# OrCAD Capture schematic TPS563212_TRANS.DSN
size D; title: TPS563212: 4.2-V to 18-V Input, 3-A Synchronous Buck; rev: 1.0; note: Datasheet: SLUSEH9     EVM: SLUUCK3; note: Synchronous Step Down Converter; note: Converter in a SOT-5X3 Package
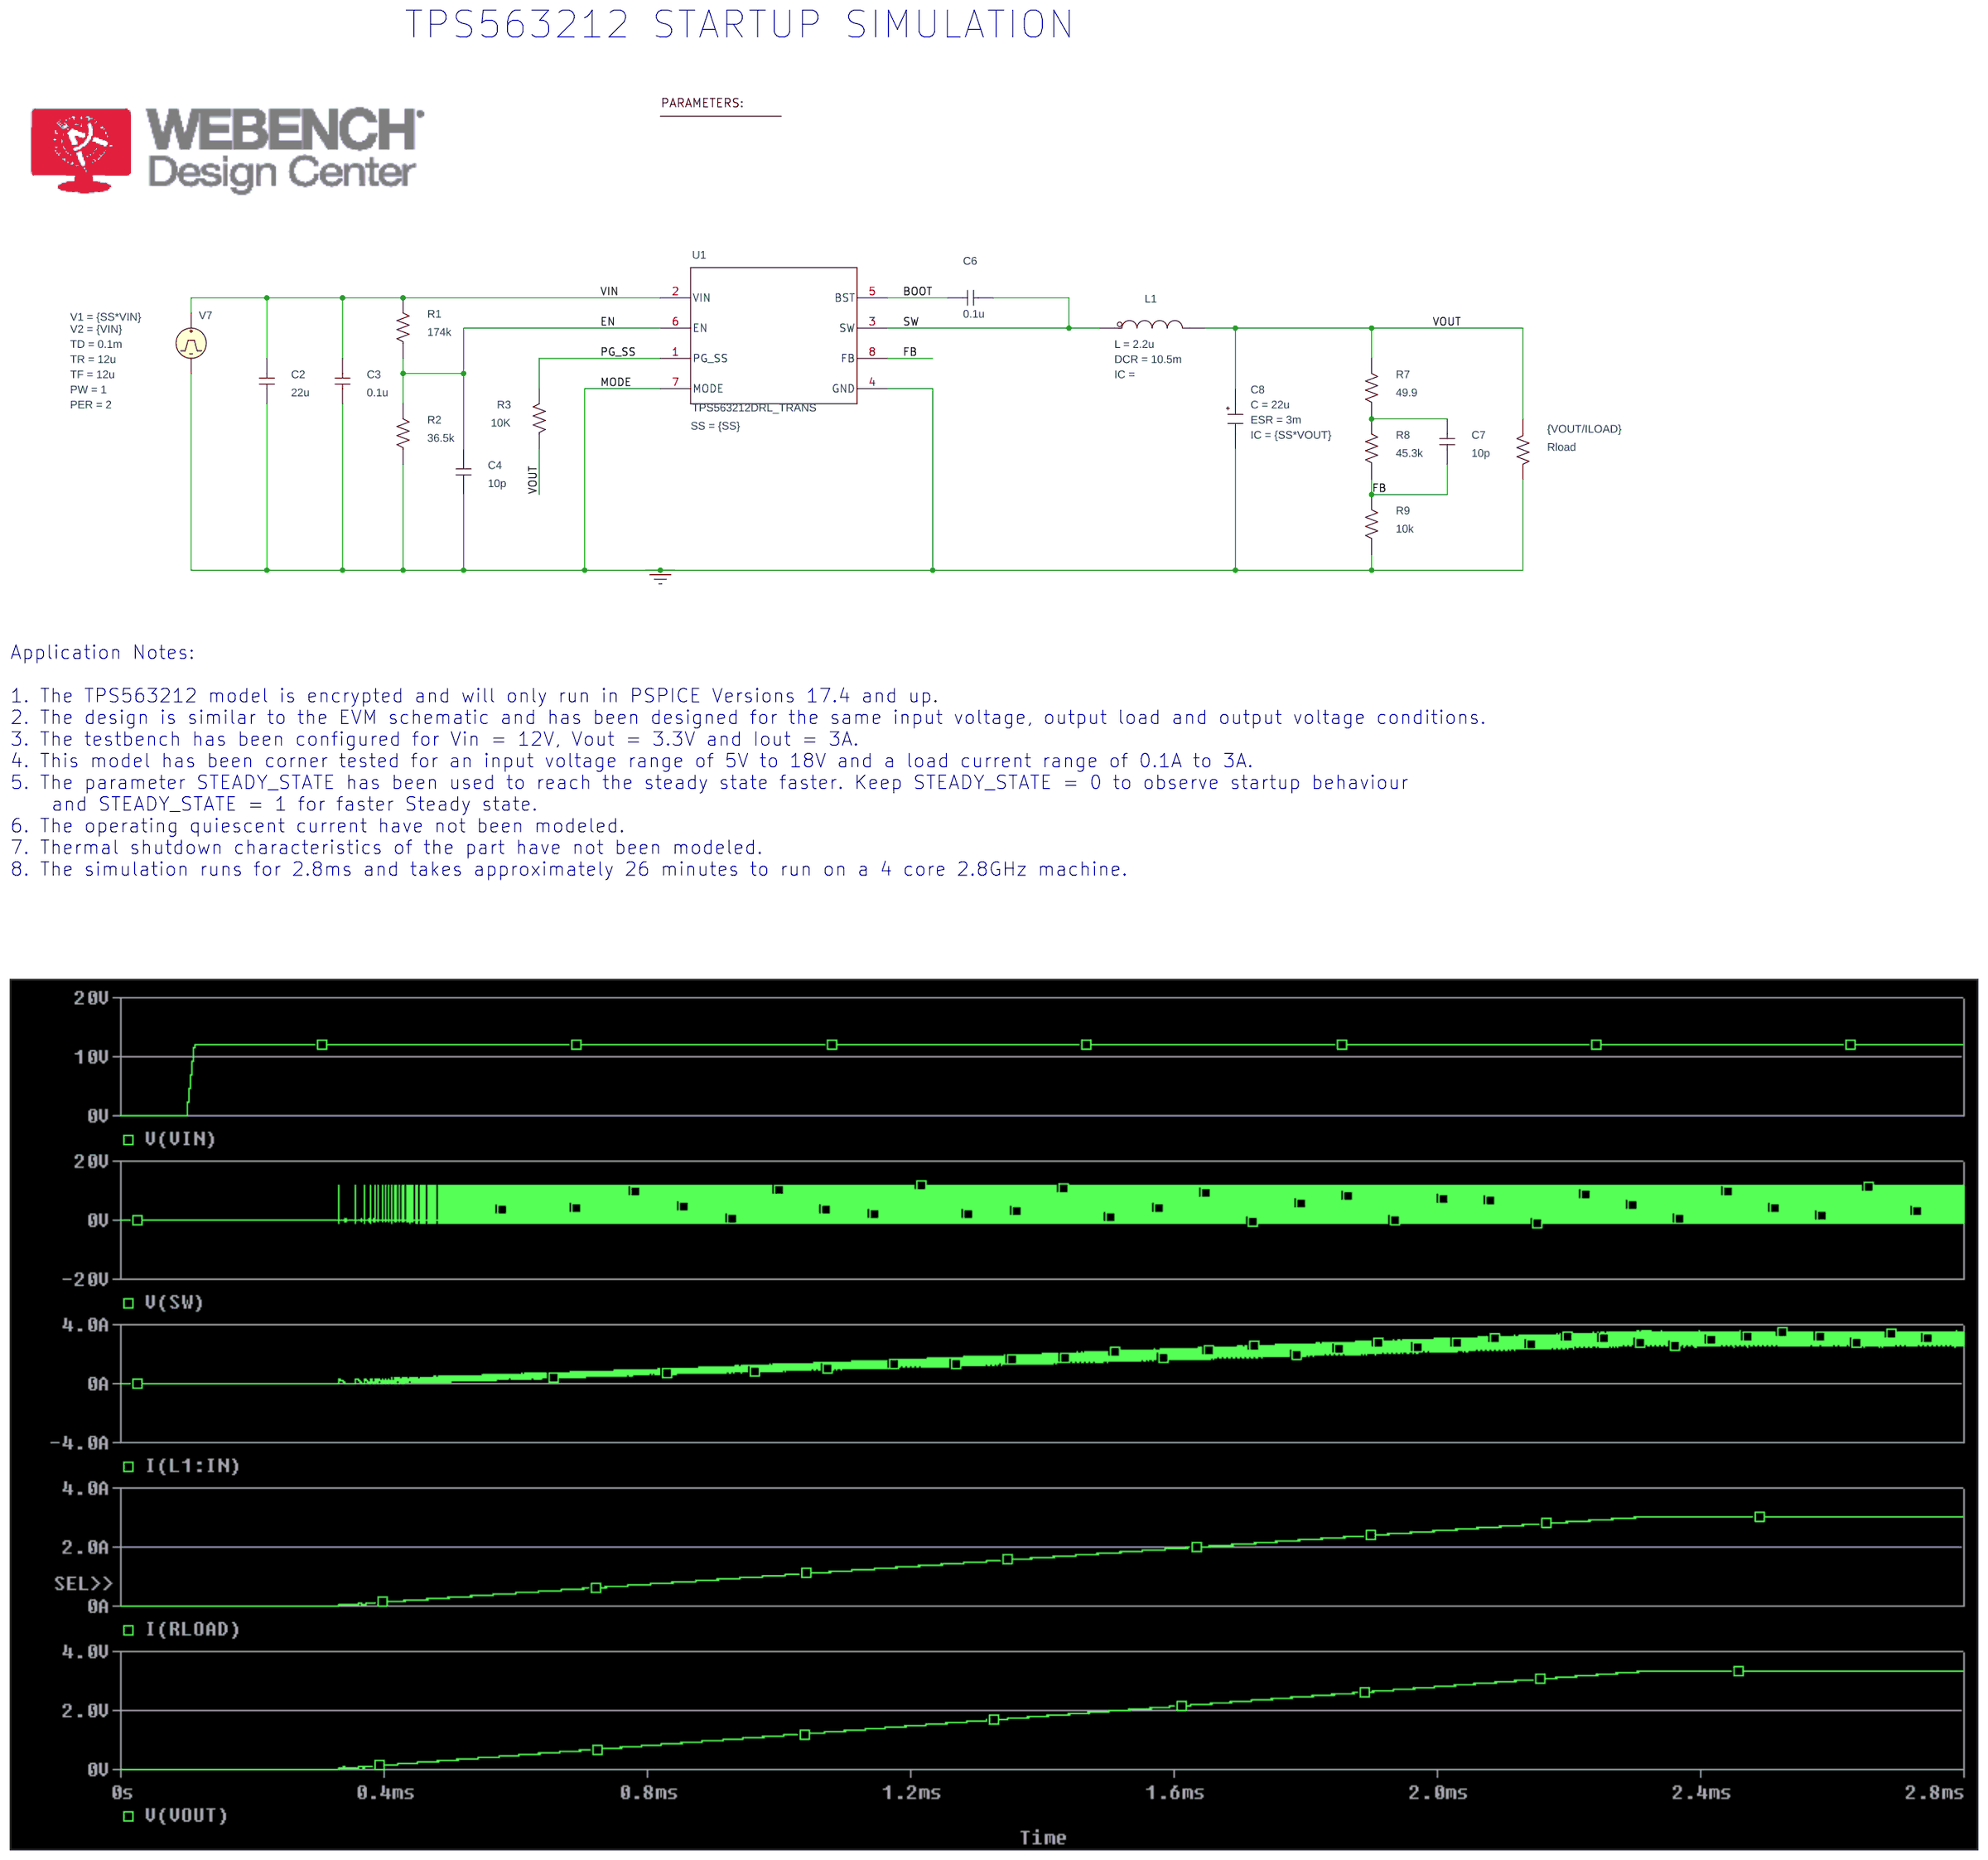
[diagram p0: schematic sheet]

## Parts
1  PARAM
C2  22u  [CK05]
C3  0.1u  [CK05]
C4  10p  [cap196]
C6  0.1u  [CK05]
C7  10p  [cap196]
C8  CESR
L1  LDCR
R1  174k  [RC05]
R2  36.5k  [RC05]
R3  10K  [AXRC05]
R7  49.9  [RC05]
R8  45.3k  [RC05]
R9  10k  [RC05]
Rload  {VOUT/ILOAD}  [AXRC05]
U1  TPS563212DRL_TRANS  [DRL0008A-MFG]
V7  VPULSE

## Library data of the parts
1 = PARAM: ILOAD: 3; SS: 0; VIN: 12; VOUT: 3.3
C2-C4 C6 C7 = C
C8 = CESR_0: C: 22u; ESR: 3m; IC: {SS*VOUT}; PSpiceTemplate: X^@REFDES %IN %OUT @MODEL PARAMS:  ?C|C=@C||C=100u|  ?ESR|ESR=@ESR||ESR=0.01| ?X|X=@X||X=2|  ?IC|IC=@IC||IC=2|; X: 1
L1 = LDCR_1: DCR: 10.5m; L: 2.2u; PSpiceTemplate: X^@REFDES %IN %OUT @MODEL PARAMS:  ?L|L=@L||L=1u|  ?DCR|DCR=@DCR||DCR=0.01|  ?IC|IC=@IC||IC=0|
R1-R3 R7-R9 Rload = R
U1 = TPS563212DRL_TRANS: SS: {SS}
V7 = VPULSE: PER: 2; PW: 1; TD: 0.1m; TF: 12u; TR: 12u; V1: {SS*VIN}; V2: {VIN}

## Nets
VIN: C2.2 C3.2 R1.2 U1.2(VIN) V7.1(+)
0: C2.1 C3.1 C4.1 C8.2(OUT) R2.1 R9.1 Rload.2 U1.4(GND) U1.7(MODE) V7.2(-)
BOOT: C6.2 U1.5(BST)
EN: C4.2 R1.1 R2.2 U1.6(EN)
FB: C7.1 R8.1 R9.2 U1.8(FB)
PG_SS: R3.2 U1.1(PG_SS)
SW: C6.1 L1.1(IN) U1.3(SW)
VOUT: C8.1(IN) L1.3(OUT) R3.1 R7.2 Rload.1
N16770157: C7.2 R7.1 R8.2

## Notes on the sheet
- TPS563212 STARTUP SIMULATION
- Application Notes:
  1. The TPS563212 model is encrypted and will only run in PSPICE Versions 17.4 and up.
  2. The design is similar to the EVM schematic and has been designed for the same input voltage, output load and output voltage conditions.
  3. The testbench has been configured for Vin = 12V, Vout = 3.3V and Iout = 3A.
  4. This model has been corner tested for an input voltage range of 5V to 18V and a load current range of 0.1A to 3A.
  5. The parameter STEADY_STATE has been used to reach the steady state faster. Keep STEADY_STATE = 0 to observe startup behaviour
      and STEADY_STATE = 1 for faster Steady state.
  6. The operating quiescent current have not been modeled.
  7. Thermal shutdown characteristics of the part have not been modeled.
  8. The simulation runs for 2.8ms and takes approximately 26 minutes to run on a 4 core 2.8GHz machine.
